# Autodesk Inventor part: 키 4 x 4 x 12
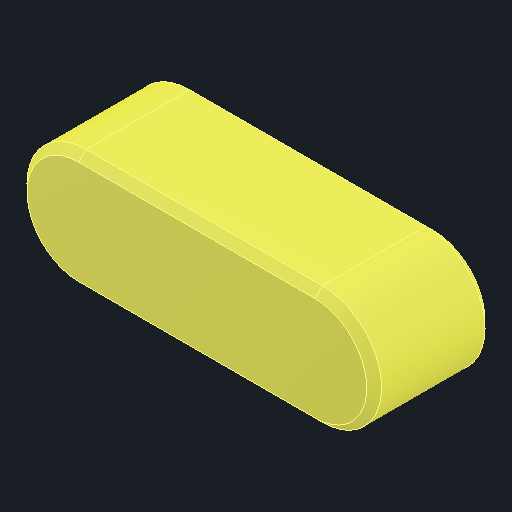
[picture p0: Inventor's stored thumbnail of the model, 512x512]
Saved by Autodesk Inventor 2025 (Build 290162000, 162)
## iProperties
Created: 2025-08
Part Number: 키 4 x 4 x 12
Material: 강철, 연강
Description: 키 및 해당 키홈
Document SubType Name: Modeling
Designer: infra10
Density: 7.85 g/cm^3
Appearance: 기본값
Author: jhkim
Sending System: Autodesk Inventor 2026
Preprocessor: ST-DEVELOPER v20.1
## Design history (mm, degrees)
feature "Solid1"
node "솔리드1"
